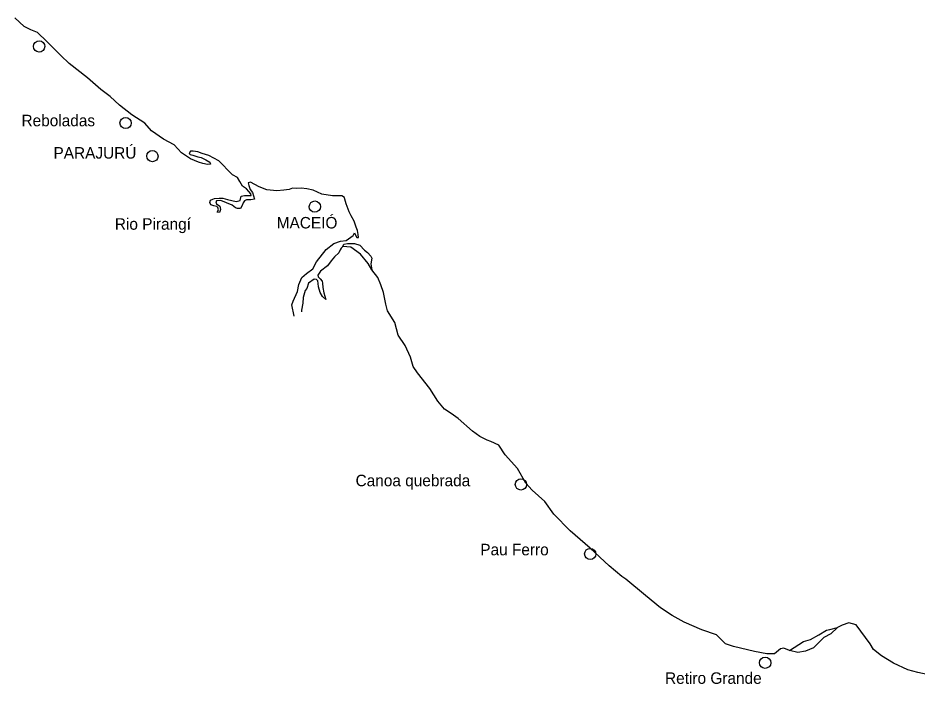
# Model space of a CAD drawing. Extents: x 662444 to 1640468, y 7452018 to 9606170.
# Drawn here: x 1284994 to 1338677, y 9480593 to 9520339 of the extents above; entities that cross this region are included whole.
import ezdxf

# ---------------------------------------------------------------- set-up
doc = ezdxf.new("R2010")
doc.units = 0
for name, color, linetype in [('Level 1', 7, 'Continuous'), ('Level 2', 7, 'Continuous'), ('Level 3', 7, 'Continuous')]:
    doc.layers.add(name, color=color, linetype=linetype)

msp = doc.modelspace()

# ---------------------------------------------------------------- linework, layer by layer
at = {"layer": 'Level 1'}
for points in [[(1298901, 9509755), (1298877, 9509837), (1298757, 9509976), (1298630, 9510139), (1298388, 9510312), (1298220, 9510590), (1298077, 9510826), (1297795, 9510983), (1297522, 9511245), (1297193, 9511589), (1296977, 9511818), (1296380, 9512140), (1295984, 9512250), (1295726, 9512349), (1295442, 9512386), (1295280, 9512387), (1295205, 9512258), (1295261, 9512200), (1295415, 9512151), (1295723, 9512058), (1295925, 9512016), (1296199, 9511883), (1296433, 9511734), (1296472, 9511613), (1296293, 9511599), (1296017, 9511649), (1295751, 9511733), (1295274, 9511933), (1294751, 9512295), (1294303, 9512770), (1293665, 9513101), (1292965, 9513610), (1292556, 9514069), (1291774, 9514563), (1291043, 9515138), (1290498, 9515646), (1289934, 9516081), (1289131, 9516778), (1288053, 9517624), (1287547, 9518098), (1286721, 9518942), (1286159, 9519475), (1285763, 9519632), (1285352, 9519831), (1284814, 9520339)], [(1301461, 9502547), (1301324, 9503229), (1301407, 9503439), (1301674, 9504012), (1301744, 9504433), (1301919, 9504844), (1302206, 9505100), (1302583, 9505372), (1302790, 9505783), (1303375, 9506515), (1303834, 9506890), (1304225, 9507016), (1304567, 9507053), (1304976, 9507365), (1305067, 9507518), (1305130, 9507371), (1305209, 9507232), (1305307, 9507232), (1305293, 9507418), (1305239, 9507653), (1305168, 9507849), (1305043, 9508224), (1304868, 9508541), (1304749, 9508778), (1304576, 9509258), (1304482, 9509518), (1304467, 9509632), (1304305, 9509731), (1304111, 9509733), (1303746, 9509736), (1303114, 9509816), (1302605, 9510065), (1302225, 9510150), (1301885, 9510185), (1301584, 9510173), (1301365, 9510175), (1301177, 9510096), (1300860, 9510067), (1300438, 9510023), (1299838, 9510094), (1299386, 9510269), (1298853, 9510533), (1298715, 9510502), (1298754, 9510333), (1298849, 9510112), (1298976, 9509925), (1299093, 9509526), (1298873, 9509480), (1298630, 9509483), (1298508, 9509419), (1298425, 9509299), (1298359, 9509145), (1298258, 9508968), (1298088, 9508970), (1297967, 9509003), (1297766, 9509176), (1297426, 9509300), (1297096, 9509451), (1296828, 9509429), (1296795, 9509372), (1296825, 9509258), (1297035, 9509103), (1297081, 9508907), (1297015, 9508737), (1296876, 9508755), (1296944, 9508893), (1296920, 9509022), (1296856, 9509080), (1296670, 9509138), (1296492, 9509181), (1296445, 9509336), (1296471, 9509473), (1296610, 9509528), (1296724, 9509568), (1296984, 9509581), (1297219, 9509579), (1297486, 9509510), (1298012, 9509392), (1298249, 9509454), (1298300, 9509705), (1298511, 9509751), (1298901, 9509755)], [(1304367, 9506698), (1304434, 9506836), (1304646, 9506890), (1305067, 9506885), (1305375, 9506777), (1305655, 9506490), (1305832, 9506343), (1306041, 9506129), (1306104, 9506015), (1306043, 9505659), (1306096, 9505310)], [(1339680, 9481054), (1338660, 9481286), (1338061, 9481430), (1337223, 9481828), (1336497, 9482275), (1336015, 9482662), (1335824, 9482997), (1334994, 9484118), (1334548, 9484236), (1334158, 9484111), (1333880, 9483968), (1333485, 9483583), (1333060, 9483378), (1332436, 9482744), (1331962, 9482562), (1331515, 9482479), (1331012, 9482590), (1330666, 9482732), (1330470, 9482685), (1330110, 9482389), (1329654, 9482395), (1328925, 9482524), (1327679, 9482831), (1327194, 9482982), (1326665, 9483532), (1325792, 9483834), (1324727, 9484292), (1324009, 9484689), (1323317, 9485135), (1322426, 9485875), (1321252, 9486844), (1321002, 9487018), (1320256, 9487643), (1319124, 9488709), (1317935, 9489737), (1316950, 9490729), (1316423, 9491480), (1315653, 9492162), (1315292, 9492571), (1314783, 9493453), (1314055, 9494279), (1313672, 9494850), (1313188, 9495059), (1312977, 9495143), (1312542, 9495366), (1312099, 9495679), (1311257, 9496434), (1310830, 9496730), (1310436, 9497003), (1310028, 9497470), (1309558, 9498220), (1308815, 9499160), (1308567, 9499536), (1308396, 9500105), (1308095, 9500790), (1307665, 9501410), (1307479, 9502167), (1307024, 9502869), (1306940, 9503266), (1306794, 9503957), (1306646, 9504405), (1306448, 9504860), (1306096, 9505310), (1305890, 9505685), (1305433, 9506250), (1304838, 9506653), (1304367, 9506698), (1304269, 9506602), (1304219, 9506506), (1304136, 9506328), (1303873, 9506088), (1303668, 9505847), (1303445, 9505542), (1303035, 9505229), (1302870, 9504988), (1302901, 9504898), (1303022, 9504776), (1303134, 9504636), (1303148, 9504507), (1303178, 9504247), (1303239, 9503930), (1303356, 9503548), (1303164, 9503720), (1303020, 9503965), (1302919, 9504299), (1302905, 9504485), (1302874, 9504648), (1302802, 9504729), (1302656, 9504747), (1302328, 9504515), (1302228, 9504192), (1302128, 9504080), (1302002, 9503651), (1301990, 9503319), (1301912, 9502907), (1301911, 9502810)], [(1331012, 9482590), (1331856, 9483132), (1332256, 9483248), (1332762, 9483535), (1333228, 9483806), (1333415, 9483844), (1333880, 9483968)]]:
    msp.add_lwpolyline(points, dxfattribs=at)
at = {"layer": 'Level 2'}
for centre, major_axis in [((1286255, 9518639), (335, -3)), ((1291412, 9514072), (335, -3)), ((1293012, 9512095), (335, -3)), ((1302700, 9509083), (335, -3)), ((1314991, 9492501), (335, -3)), ((1319128, 9488352), (335, -3)), ((1329559, 9481861), (338, -3))]:
    msp.add_ellipse(centre, major_axis=major_axis, ratio=0.999998, dxfattribs=at)

# ---------------------------------------------------------------- texts
at = {"layer": 'Level 3'}
for s, height, p in [('Reboladas', 686.3, (1285203, 9513878)), ('PARAJURÚ', 686.3, (1287111, 9511947)), ('Rio Pirangí', 686.32, (1290771, 9507703)), ('MACEIÓ', 686.4, (1300425, 9507778)), ('Canoa quebrada', 686.41, (1305130, 9492395)), ('Pau Ferro', 686.4, (1312568, 9488273)), ('Retiro Grande', 686.56, (1323587, 9480603))]:
    msp.add_text(s, height=height, dxfattribs=at).set_placement(p)

doc.saveas('drawing.dxf')
